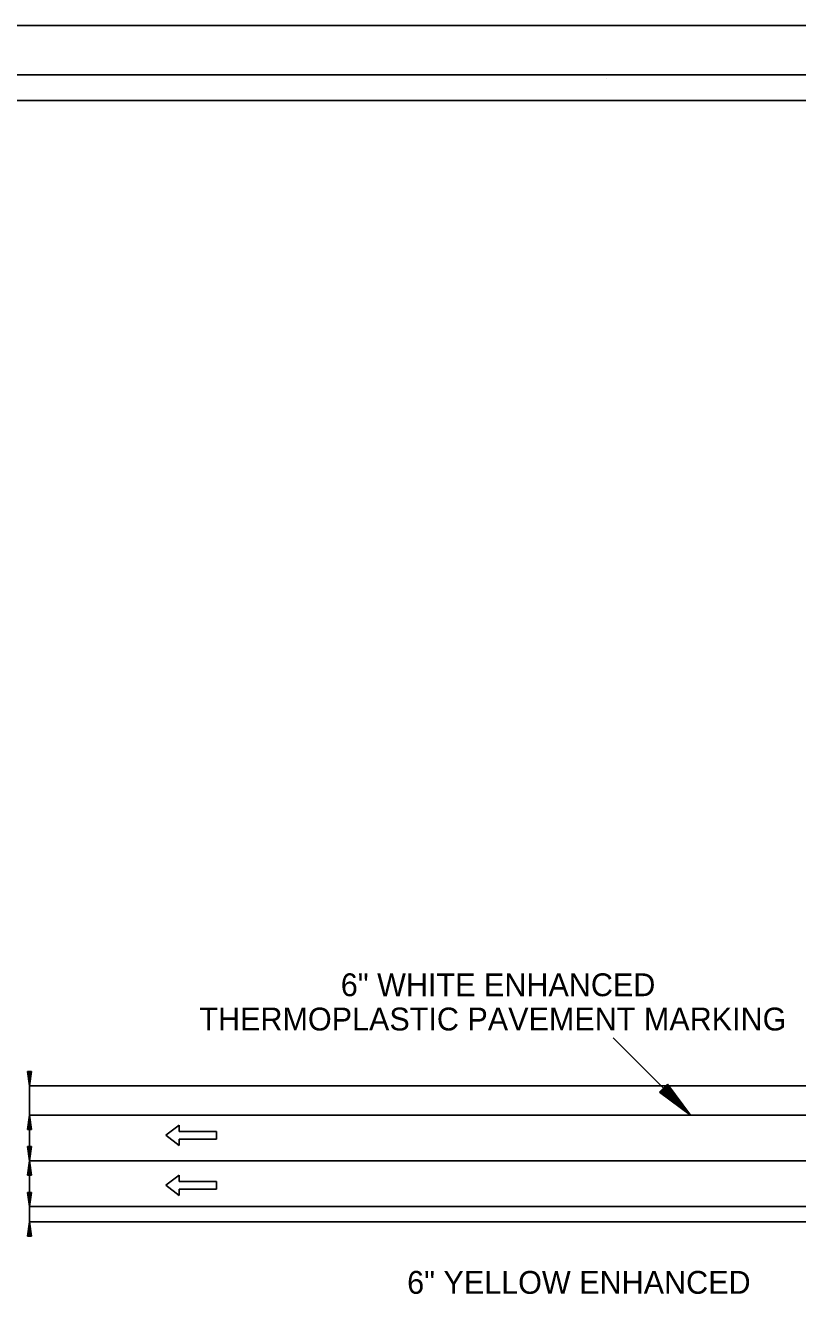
# Model space of a CAD drawing. Extents: x 1369905 to 1370238, y 380119 to 380332.
# Drawn here: x 1370023.8 to 1370084.7, y 380232.1 to 380332.4 of the extents above; entities that cross this region are included whole.
import ezdxf

# ---------------------------------------------------------------- set-up
doc = ezdxf.new("R2010")
doc.units = 0
for name, color, linetype in [('Default', 7, 'Continuous'), ('R_Border', 7, 'Continuous'), ('R_Horz Alg', 7, 'Continuous'), ('R_MOT', 7, 'Continuous'), ('R_No Plot', 7, 'Continuous'), ('R_Proposed Road', 7, 'Continuous')]:
    doc.layers.add(name, color=color, linetype=linetype)

# ---------------------------------------------------------------- blocks, each defined once
blk = doc.blocks.new('SARROW')
at = {"layer": 'Default'}
for p, q in [((15.6, 3.2), (-13.8, 3.2)), ((-13.8, 3.2), (-13.8, -2.8)), ((15.6, 8.2), (15.6, 3.2)), ((15.6, 8.2), (26, 0.2)), ((26, 0.2), (15.6, -7.8)), ((15.6, -2.8), (-13.8, -2.8)), ((15.6, -2.8), (15.6, -7.8))]:
    blk.add_line(p, q, dxfattribs=at)

msp = doc.modelspace()

# ---------------------------------------------------------------- linework, layer by layer
at = {"layer": 'Default'}
for p, q in [((1370023.95, 380250.04), (1370024.12, 380248.91)), ((1370024.29, 380250.04), (1370023.95, 380250.04)), ((1370023.98, 380250.04), (1370024.12, 380249.1)), ((1370024, 380250.04), (1370024.12, 380249.3)), ((1370024.04, 380250.04), (1370024.12, 380249.48)), ((1370024.06, 380250.04), (1370024.12, 380249.68)), ((1370024.09, 380250.04), (1370024.12, 380249.86)), ((1370024.29, 380250.04), (1370024.12, 380248.91)), ((1370024.17, 380250.04), (1370024.12, 380249.68)), ((1370024.23, 380250.04), (1370024.12, 380249.3)), ((1370024.26, 380250.04), (1370024.12, 380249.1)), ((1370024.2, 380250.04), (1370024.12, 380249.48)), ((1370024.14, 380250.04), (1370024.12, 380249.86)), ((1370074.42, 380249.03), (1370073.78, 380248.39)), ((1370074.42, 380249.03), (1370073.78, 380248.39)), ((1370074.42, 380249.03), (1370073.78, 380248.39)), ((1370074.42, 380249.03), (1370076.22, 380246.59)), ((1370074.42, 380249.03), (1370076.22, 380246.59)), ((1370074.42, 380249.03), (1370076.22, 380246.59)), ((1370073.78, 380248.39), (1370076.22, 380246.59)), ((1370073.78, 380248.39), (1370076.22, 380246.59)), ((1370073.78, 380248.39), (1370076.22, 380246.59)), ((1370073.84, 380248.45), (1370075.87, 380246.94)), ((1370073.84, 380248.45), (1370075.87, 380246.94)), ((1370073.84, 380248.45), (1370075.87, 380246.94)), ((1370073.89, 380248.5), (1370075.5, 380247.31)), ((1370073.89, 380248.5), (1370075.5, 380247.31)), ((1370073.89, 380248.5), (1370075.5, 380247.31)), ((1370073.95, 380248.56), (1370075.15, 380247.66)), ((1370073.95, 380248.56), (1370075.15, 380247.66)), ((1370073.95, 380248.56), (1370075.15, 380247.66)), ((1370073.99, 380248.6), (1370074.79, 380248.02)), ((1370073.99, 380248.6), (1370074.79, 380248.02)), ((1370073.99, 380248.6), (1370074.79, 380248.02)), ((1370074.05, 380248.66), (1370074.43, 380248.38)), ((1370074.05, 380248.66), (1370074.43, 380248.38)), ((1370074.05, 380248.66), (1370074.43, 380248.38)), ((1370074.15, 380248.76), (1370074.43, 380248.38)), ((1370074.15, 380248.76), (1370074.43, 380248.38)), ((1370074.15, 380248.76), (1370074.43, 380248.38)), ((1370074.21, 380248.82), (1370074.79, 380248.02)), ((1370074.21, 380248.82), (1370074.79, 380248.02)), ((1370074.21, 380248.82), (1370074.79, 380248.02)), ((1370074.26, 380248.86), (1370075.15, 380247.66)), ((1370074.26, 380248.86), (1370075.15, 380247.66)), ((1370074.26, 380248.86), (1370075.15, 380247.66)), ((1370074.31, 380248.92), (1370075.5, 380247.31)), ((1370074.31, 380248.92), (1370075.5, 380247.31)), ((1370074.31, 380248.92), (1370075.5, 380247.31)), ((1370074.36, 380248.97), (1370075.87, 380246.94)), ((1370074.36, 380248.97), (1370075.87, 380246.94)), ((1370074.36, 380248.97), (1370075.87, 380246.94)), ((1370023.95, 380245.46), (1370024.12, 380246.59)), ((1370023.95, 380245.46), (1370024.12, 380246.59)), ((1370023.95, 380245.46), (1370024.12, 380246.59)), ((1370023.98, 380245.46), (1370024.12, 380246.4)), ((1370023.98, 380245.46), (1370024.12, 380246.4)), ((1370023.98, 380245.46), (1370024.12, 380246.4)), ((1370024, 380245.46), (1370024.12, 380246.21)), ((1370024, 380245.46), (1370024.12, 380246.21)), ((1370024, 380245.46), (1370024.12, 380246.21)), ((1370024.04, 380245.46), (1370024.12, 380246.02)), ((1370024.04, 380245.46), (1370024.12, 380246.02)), ((1370024.04, 380245.46), (1370024.12, 380246.02)), ((1370024.29, 380245.46), (1370024.12, 380246.59)), ((1370024.29, 380245.46), (1370024.12, 380246.59)), ((1370024.29, 380245.46), (1370024.12, 380246.59)), ((1370024.26, 380245.46), (1370024.12, 380246.4)), ((1370024.26, 380245.46), (1370024.12, 380246.4)), ((1370024.26, 380245.46), (1370024.12, 380246.4)), ((1370024.23, 380245.46), (1370024.12, 380246.21)), ((1370024.23, 380245.46), (1370024.12, 380246.21)), ((1370024.23, 380245.46), (1370024.12, 380246.21)), ((1370024.2, 380245.46), (1370024.12, 380246.02)), ((1370024.2, 380245.46), (1370024.12, 380246.02)), ((1370024.2, 380245.46), (1370024.12, 380246.02)), ((1370023.95, 380245.46), (1370024.29, 380245.46)), ((1370023.95, 380245.46), (1370024.29, 380245.46)), ((1370023.95, 380245.46), (1370024.29, 380245.46)), ((1370024.06, 380245.46), (1370024.12, 380245.83)), ((1370024.06, 380245.46), (1370024.12, 380245.83)), ((1370024.06, 380245.46), (1370024.12, 380245.83)), ((1370024.09, 380245.46), (1370024.12, 380245.64)), ((1370024.09, 380245.46), (1370024.12, 380245.64)), ((1370024.09, 380245.46), (1370024.12, 380245.64)), ((1370024.17, 380245.46), (1370024.12, 380245.83)), ((1370024.17, 380245.46), (1370024.12, 380245.83)), ((1370024.17, 380245.46), (1370024.12, 380245.83)), ((1370024.14, 380245.46), (1370024.12, 380245.64)), ((1370024.14, 380245.46), (1370024.12, 380245.64)), ((1370024.14, 380245.46), (1370024.12, 380245.64)), ((1370023.95, 380244.11), (1370024.12, 380242.99)), ((1370024.29, 380244.11), (1370023.95, 380244.11)), ((1370023.95, 380244.11), (1370024.12, 380242.99)), ((1370024.29, 380244.11), (1370023.95, 380244.11)), ((1370023.95, 380244.11), (1370024.12, 380242.99)), ((1370024.29, 380244.11), (1370023.95, 380244.11)), ((1370023.98, 380244.11), (1370024.12, 380243.18)), ((1370023.98, 380244.11), (1370024.12, 380243.18)), ((1370023.98, 380244.11), (1370024.12, 380243.18)), ((1370024, 380244.11), (1370024.12, 380243.37)), ((1370024, 380244.11), (1370024.12, 380243.37)), ((1370024, 380244.11), (1370024.12, 380243.37)), ((1370024.04, 380244.11), (1370024.12, 380243.56)), ((1370024.04, 380244.11), (1370024.12, 380243.56)), ((1370024.04, 380244.11), (1370024.12, 380243.56)), ((1370024.06, 380244.11), (1370024.12, 380243.75)), ((1370024.06, 380244.11), (1370024.12, 380243.75)), ((1370024.06, 380244.11), (1370024.12, 380243.75)), ((1370024.09, 380244.11), (1370024.12, 380243.94)), ((1370024.09, 380244.11), (1370024.12, 380243.94)), ((1370024.09, 380244.11), (1370024.12, 380243.94)), ((1370024.29, 380244.11), (1370024.12, 380242.99)), ((1370024.17, 380244.11), (1370024.12, 380243.75)), ((1370024.23, 380244.11), (1370024.12, 380243.37)), ((1370024.26, 380244.11), (1370024.12, 380243.18)), ((1370024.2, 380244.11), (1370024.12, 380243.56)), ((1370024.14, 380244.11), (1370024.12, 380243.94)), ((1370024.29, 380244.11), (1370024.12, 380242.99)), ((1370024.17, 380244.11), (1370024.12, 380243.75)), ((1370024.23, 380244.11), (1370024.12, 380243.37)), ((1370024.26, 380244.11), (1370024.12, 380243.18)), ((1370024.2, 380244.11), (1370024.12, 380243.56)), ((1370024.14, 380244.11), (1370024.12, 380243.94)), ((1370024.29, 380244.11), (1370024.12, 380242.99)), ((1370024.17, 380244.11), (1370024.12, 380243.75)), ((1370024.23, 380244.11), (1370024.12, 380243.37)), ((1370024.26, 380244.11), (1370024.12, 380243.18)), ((1370024.2, 380244.11), (1370024.12, 380243.56)), ((1370024.14, 380244.11), (1370024.12, 380243.94)), ((1370023.95, 380241.86), (1370024.12, 380242.99)), ((1370023.95, 380241.86), (1370024.12, 380242.99)), ((1370023.95, 380241.86), (1370024.12, 380242.99)), ((1370024.29, 380241.86), (1370024.12, 380242.99)), ((1370024.29, 380241.86), (1370024.12, 380242.99)), ((1370024.29, 380241.86), (1370024.12, 380242.99)), ((1370023.98, 380241.86), (1370024.12, 380242.8)), ((1370023.98, 380241.86), (1370024.12, 380242.8)), ((1370023.98, 380241.86), (1370024.12, 380242.8)), ((1370024, 380241.86), (1370024.12, 380242.61)), ((1370024, 380241.86), (1370024.12, 380242.61)), ((1370024, 380241.86), (1370024.12, 380242.61)), ((1370024.04, 380241.86), (1370024.12, 380242.42)), ((1370024.04, 380241.86), (1370024.12, 380242.42)), ((1370024.04, 380241.86), (1370024.12, 380242.42)), ((1370024.06, 380241.86), (1370024.12, 380242.23)), ((1370024.06, 380241.86), (1370024.12, 380242.23)), ((1370024.06, 380241.86), (1370024.12, 380242.23)), ((1370024.09, 380241.86), (1370024.12, 380242.04)), ((1370024.09, 380241.86), (1370024.12, 380242.04)), ((1370024.09, 380241.86), (1370024.12, 380242.04)), ((1370024.26, 380241.86), (1370024.12, 380242.8)), ((1370024.26, 380241.86), (1370024.12, 380242.8)), ((1370024.26, 380241.86), (1370024.12, 380242.8)), ((1370024.23, 380241.86), (1370024.12, 380242.61)), ((1370024.23, 380241.86), (1370024.12, 380242.61)), ((1370024.23, 380241.86), (1370024.12, 380242.61)), ((1370024.2, 380241.86), (1370024.12, 380242.42)), ((1370024.2, 380241.86), (1370024.12, 380242.42)), ((1370024.2, 380241.86), (1370024.12, 380242.42)), ((1370024.17, 380241.86), (1370024.12, 380242.23)), ((1370024.17, 380241.86), (1370024.12, 380242.23)), ((1370024.17, 380241.86), (1370024.12, 380242.23)), ((1370024.14, 380241.86), (1370024.12, 380242.04)), ((1370024.14, 380241.86), (1370024.12, 380242.04)), ((1370024.14, 380241.86), (1370024.12, 380242.04)), ((1370023.95, 380241.86), (1370024.29, 380241.86)), ((1370023.95, 380241.86), (1370024.29, 380241.86)), ((1370023.95, 380241.86), (1370024.29, 380241.86)), ((1370023.95, 380240.51), (1370024.12, 380239.39)), ((1370024.29, 380240.51), (1370023.95, 380240.51)), ((1370023.95, 380240.51), (1370024.12, 380239.39)), ((1370024.29, 380240.51), (1370023.95, 380240.51)), ((1370023.95, 380240.51), (1370024.12, 380239.39)), ((1370024.29, 380240.51), (1370023.95, 380240.51)), ((1370023.98, 380240.51), (1370024.12, 380239.58)), ((1370023.98, 380240.51), (1370024.12, 380239.58)), ((1370023.98, 380240.51), (1370024.12, 380239.58)), ((1370024, 380240.51), (1370024.12, 380239.77)), ((1370024, 380240.51), (1370024.12, 380239.77)), ((1370024, 380240.51), (1370024.12, 380239.77)), ((1370024.04, 380240.51), (1370024.12, 380239.96)), ((1370024.04, 380240.51), (1370024.12, 380239.96)), ((1370024.04, 380240.51), (1370024.12, 380239.96)), ((1370024.06, 380240.51), (1370024.12, 380240.15)), ((1370024.06, 380240.51), (1370024.12, 380240.15)), ((1370024.06, 380240.51), (1370024.12, 380240.15)), ((1370024.09, 380240.51), (1370024.12, 380240.34)), ((1370024.09, 380240.51), (1370024.12, 380240.34)), ((1370024.09, 380240.51), (1370024.12, 380240.34)), ((1370024.29, 380240.51), (1370024.12, 380239.39)), ((1370024.17, 380240.51), (1370024.12, 380240.15)), ((1370024.23, 380240.51), (1370024.12, 380239.77)), ((1370024.26, 380240.51), (1370024.12, 380239.58)), ((1370024.2, 380240.51), (1370024.12, 380239.96)), ((1370024.14, 380240.51), (1370024.12, 380240.34)), ((1370024.29, 380240.51), (1370024.12, 380239.39)), ((1370024.17, 380240.51), (1370024.12, 380240.15)), ((1370024.23, 380240.51), (1370024.12, 380239.77)), ((1370024.26, 380240.51), (1370024.12, 380239.58)), ((1370024.2, 380240.51), (1370024.12, 380239.96)), ((1370024.14, 380240.51), (1370024.12, 380240.34)), ((1370024.29, 380240.51), (1370024.12, 380239.39)), ((1370024.17, 380240.51), (1370024.12, 380240.15)), ((1370024.23, 380240.51), (1370024.12, 380239.77)), ((1370024.26, 380240.51), (1370024.12, 380239.58)), ((1370024.2, 380240.51), (1370024.12, 380239.96)), ((1370024.14, 380240.51), (1370024.12, 380240.34)), ((1370023.95, 380237.06), (1370024.12, 380238.19)), ((1370023.98, 380237.06), (1370024.12, 380238)), ((1370024.29, 380237.06), (1370024.12, 380238.19)), ((1370024.26, 380237.06), (1370024.12, 380238)), ((1370023.95, 380237.06), (1370024.29, 380237.06)), ((1370024, 380237.06), (1370024.12, 380237.81)), ((1370024.04, 380237.06), (1370024.12, 380237.62)), ((1370024.06, 380237.06), (1370024.12, 380237.43)), ((1370024.09, 380237.06), (1370024.12, 380237.24)), ((1370024.23, 380237.06), (1370024.12, 380237.81)), ((1370024.2, 380237.06), (1370024.12, 380237.62)), ((1370024.17, 380237.06), (1370024.12, 380237.43)), ((1370024.14, 380237.06), (1370024.12, 380237.24))]:
    msp.add_line(p, q, dxfattribs=at)
at = {"layer": 'R_Border'}
for p, q in [((1369917.1, 380328.52), (1370233.28, 380328.52)), ((1370069.62, 380328.26), (1370069.62, 380328.26)), ((1370069.62, 380328.26), (1370069.62, 380328.26))]:
    msp.add_line(p, q, dxfattribs=at)
at = {"layer": 'R_Horz Alg'}
msp.add_line((1370024.12, 380242.99), (1370129.12, 380242.99), dxfattribs=at)
at = {"layer": 'R_No Plot'}
for points in [[(1369904.69, 380332.42), (1370238.03, 380332.42), (1370238.03, 380119.08), (1369904.69, 380119.08)], [(1370231.28, 380227.79), (1369919.1, 380227.79), (1369919.1, 380326.52), (1370168.64, 380326.52), (1370168.64, 380316.64), (1370186.18, 380316.64), (1370210.28, 380316.64), (1370210.28, 380294.31), (1370231.28, 380294.31)], [(1369919.1, 380326.52), (1370168.64, 380326.52), (1370168.64, 380316.64), (1370186.18, 380316.64), (1370210.28, 380316.64), (1370210.28, 380294.31), (1370231.28, 380294.31), (1370231.28, 380125.06), (1369919.1, 380125.06)]]:
    msp.add_lwpolyline(points, close=True, dxfattribs=at)
at = {"layer": 'R_Proposed Road'}
for p, q in [((1370070.14, 380252.67), (1370076.22, 380246.59)), ((1370070.14, 380252.67), (1370076.22, 380246.59)), ((1370070.14, 380252.67), (1370076.22, 380246.59)), ((1370024.12, 380246.59), (1370024.12, 380248.91)), ((1370024.12, 380248.91), (1370129.12, 380248.91)), ((1370024.12, 380242.99), (1370024.12, 380246.59)), ((1370024.12, 380246.59), (1370129.12, 380246.59)), ((1370024.12, 380242.99), (1370024.12, 380246.59)), ((1370024.12, 380242.99), (1370024.12, 380246.59)), ((1370024.12, 380239.39), (1370024.12, 380242.99)), ((1370024.12, 380239.39), (1370024.12, 380242.99)), ((1370024.12, 380239.39), (1370024.12, 380242.99)), ((1370024.12, 380239.39), (1370129.12, 380239.39)), ((1370024.12, 380238.19), (1370024.12, 380239.39)), ((1370024.12, 380238.19), (1370129.12, 380238.19))]:
    msp.add_line(p, q, dxfattribs=at)

# ---------------------------------------------------------------- block references
at = {"layer": 'R_MOT', "xscale": 0.1, "yscale": 0.10000000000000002, "rotation": -179.99999999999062}
for p in [(1370037.47, 380245.03), (1370037.47, 380241.09)]:
    msp.add_blockref('SARROW', p, dxfattribs=at)

# ---------------------------------------------------------------- texts
at = {"layer": 'Default'}
for s, p in [('6" WHITE ENHANCED ', (1370048.66, 380255.96)), ('THERMOPLASTIC PAVEMENT MARKING', (1370037.51, 380253.26)), ('6" YELLOW ENHANCED ', (1370053.89, 380232.52))]:
    msp.add_text(s, height=1.8, dxfattribs=at).set_placement(p)

doc.saveas('drawing.dxf')
